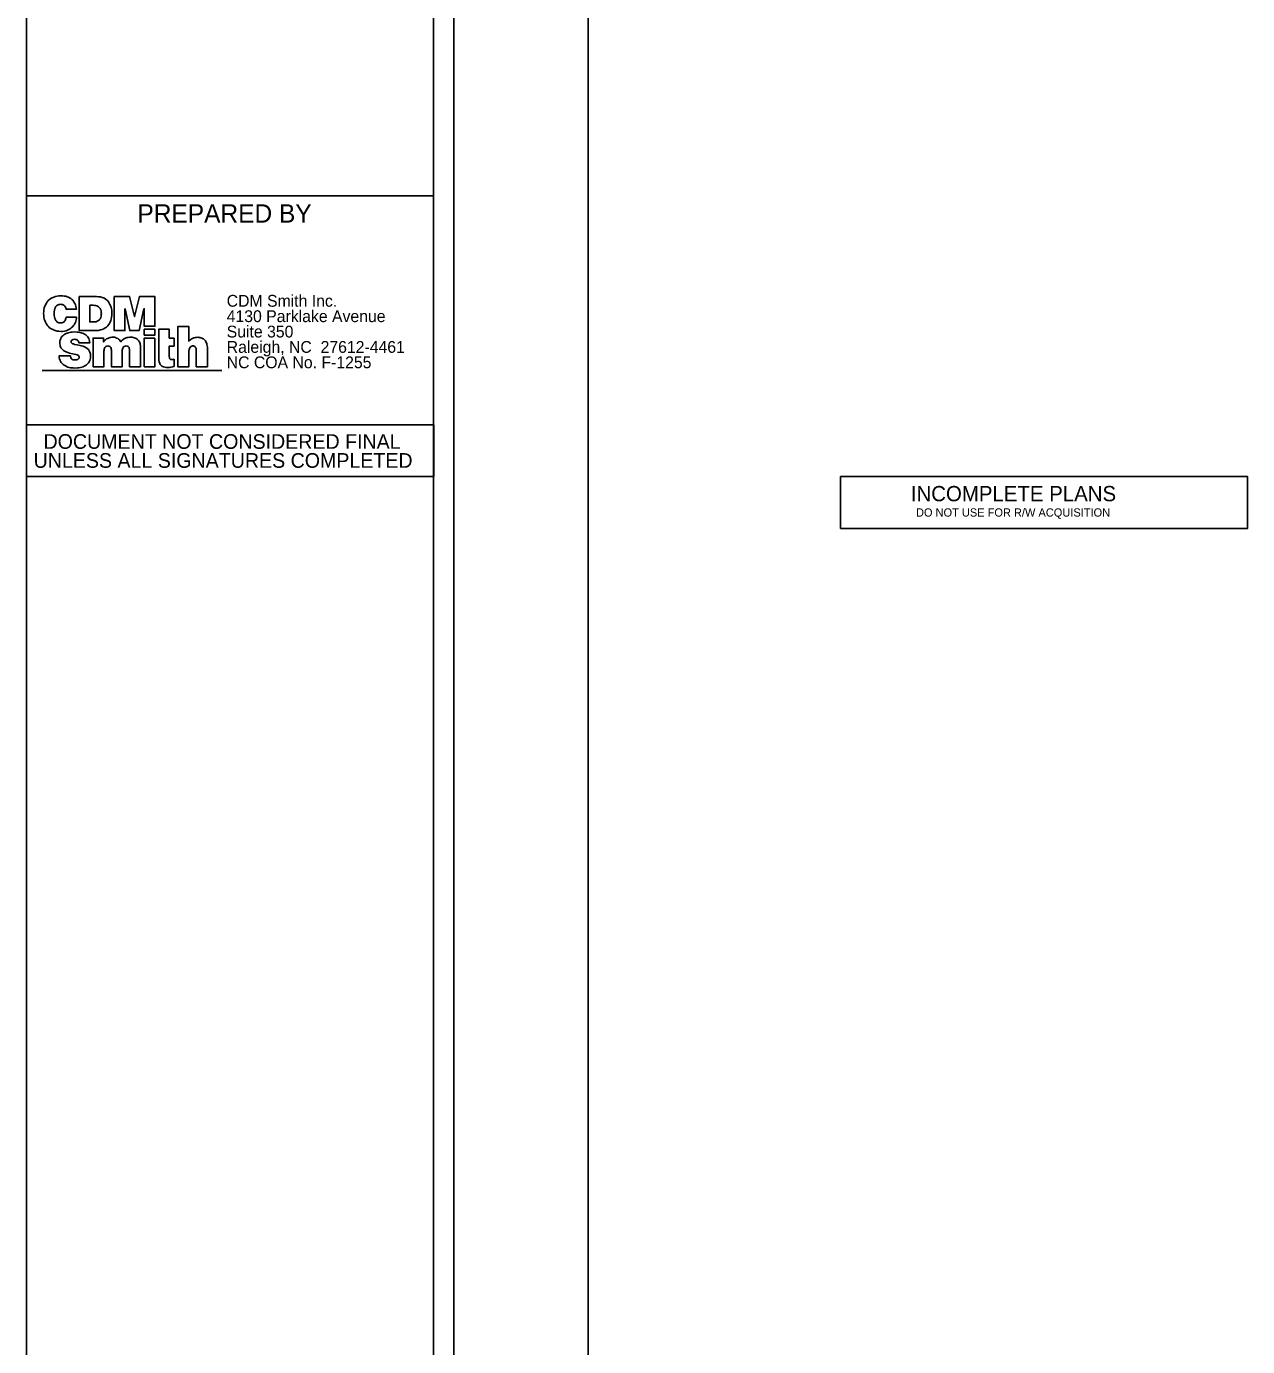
# Model space of a CAD drawing. Extents: x -2362 to 1945, y 0 to 1100.
# Drawn here: x 1562 to 1862, y 451.4 to 775.7 of the extents above; entities that cross this region are included whole.
import ezdxf

# ---------------------------------------------------------------- set-up
doc = ezdxf.new("R2010")
doc.units = 0
for name, color, linetype in [('Exist Utilities Telephone Test Hole SUE LOS A CELL', 7, 'Continuous'), ('Sheet PE Seal CELL', 7, 'Continuous'), ('Sheet_Data_Field_CELL', 7, 'Continuous'), ('z - Construction', 7, 'Continuous')]:
    doc.layers.add(name, color=color, linetype=linetype)

msp = doc.modelspace()

# ---------------------------------------------------------------- linework, layer by layer
at = {"layer": 'Exist Utilities Telephone Test Hole SUE LOS A CELL'}
msp.add_line((1699.98, 0), (1699.98, 1100), dxfattribs=at)
at = {"layer": 'Sheet PE Seal CELL'}
for p, q in [((1661.97, 734.06), (1561.97, 734.06)), ((1662.03, 677.87), (1562.03, 677.87))]:
    msp.add_line(p, q, dxfattribs=at)
for points in [[(1562.03, 677.87), (1662.03, 677.87), (1662.03, 665.13), (1562.03, 665.13)], [(1761.99, 665.13), (1861.99, 665.13), (1861.99, 652.39), (1761.99, 652.39)]]:
    msp.add_lwpolyline(points, close=True, dxfattribs=at)
at = {"layer": 'Sheet_Data_Field_CELL'}
msp.add_line((1565.85, 691.15), (1610.01, 691.15), dxfattribs=at)
for points in [[(1569.12, 703.6), (1569.04, 703.77), (1568.98, 703.94), (1568.87, 704.34), (1568.81, 704.73), (1568.78, 705.16), (1568.81, 705.59), (1568.87, 705.98), (1568.98, 706.38), (1569.04, 706.55), (1569.12, 706.72), (1569.23, 706.89), (1569.35, 707.04), (1569.46, 707.15), (1569.63, 707.26), (1569.77, 707.35), (1569.97, 707.41), (1570.17, 707.43), (1570.37, 707.46), (1570.57, 707.43), (1570.74, 707.41), (1570.88, 707.38), (1571.02, 707.32), (1571.17, 707.23), (1571.25, 707.15), (1571.42, 706.95), (1571.56, 706.75), (1571.65, 706.55), (1571.71, 706.35), (1571.73, 706.24), (1574.24, 706.24), (1574.18, 706.61), (1574.09, 706.98), (1574.01, 707.32), (1573.87, 707.63), (1573.72, 707.92), (1573.55, 708.2), (1573.35, 708.46), (1573.13, 708.66), (1572.87, 708.85), (1572.59, 709.05), (1572.3, 709.2), (1571.99, 709.31), (1571.62, 709.42), (1571.25, 709.48), (1570.85, 709.54), (1570.46, 709.54), (1569.97, 709.54), (1569.52, 709.45), (1569.09, 709.37), (1568.69, 709.22), (1568.33, 709.05), (1567.98, 708.85), (1567.64, 708.6), (1567.36, 708.34), (1567.1, 708.03), (1566.88, 707.72), (1566.68, 707.35), (1566.51, 706.95), (1566.36, 706.55), (1566.28, 706.1), (1566.22, 705.64), (1566.19, 705.16), (1566.22, 704.71), (1566.28, 704.25), (1566.36, 703.83), (1566.48, 703.43), (1566.65, 703.06), (1566.82, 702.69), (1567.05, 702.35), (1567.3, 702.03), (1567.59, 701.75), (1567.93, 701.52), (1568.27, 701.3), (1568.64, 701.13), (1569.04, 700.98), (1569.49, 700.87), (1569.94, 700.81), (1570.46, 700.78), (1570.88, 700.78), (1571.31, 700.87), (1571.71, 700.96), (1572.08, 701.1), (1572.42, 701.24), (1572.73, 701.44), (1573.01, 701.64), (1573.27, 701.89), (1573.5, 702.15), (1573.7, 702.4), (1573.87, 702.72), (1574.01, 703), (1574.12, 703.31), (1574.21, 703.63), (1574.26, 703.94), (1574.26, 704.25), (1571.73, 704.25), (1571.68, 703.97), (1571.59, 703.71), (1571.48, 703.48), (1571.34, 703.26), (1571.14, 703.09), (1570.94, 702.97), (1570.68, 702.89), (1570.37, 702.86), (1570.17, 702.89), (1569.97, 702.92), (1569.77, 702.97), (1569.63, 703.06), (1569.46, 703.17), (1569.35, 703.29), (1569.23, 703.43), (1569.12, 703.6)], [(1582.96, 704.71), (1582.96, 705.16), (1582.96, 705.56), (1582.93, 705.96), (1582.84, 706.35), (1582.76, 706.72), (1582.65, 707.06), (1582.5, 707.43), (1582.33, 707.75), (1582.13, 708.06), (1581.88, 708.34), (1581.62, 708.57), (1581.31, 708.8), (1580.97, 709), (1580.57, 709.14), (1580.15, 709.25), (1579.69, 709.31), (1579.18, 709.34), (1574.95, 709.34), (1574.95, 700.98), (1578.7, 700.98), (1579.21, 700.98), (1579.72, 701.04), (1580.17, 701.15), (1580.6, 701.27), (1580.97, 701.44), (1581.34, 701.64), (1581.65, 701.86), (1581.94, 702.12), (1582.16, 702.4), (1582.39, 702.72), (1582.56, 703.06), (1582.7, 703.43), (1582.82, 703.82), (1582.9, 704.25), (1582.96, 704.71)], [(1577.53, 707.21), (1578.36, 707.21), (1578.7, 707.18), (1578.98, 707.15), (1579.24, 707.06), (1579.46, 706.95), (1579.66, 706.84), (1579.83, 706.69), (1579.95, 706.55), (1580.06, 706.41), (1580.17, 706.24), (1580.23, 706.07), (1580.34, 705.73), (1580.37, 705.44), (1580.4, 705.22), (1580.37, 704.9), (1580.32, 704.56), (1580.23, 704.19), (1580.15, 704.02), (1580.06, 703.88), (1579.97, 703.71), (1579.83, 703.57), (1579.69, 703.46), (1579.52, 703.34), (1579.32, 703.26), (1579.09, 703.17), (1578.84, 703.14), (1578.55, 703.11), (1577.53, 703.11), (1577.53, 707.21)], [(1586.17, 706.35), (1586.23, 706.35), (1587.36, 700.98), (1589.64, 700.98), (1590.86, 706.35), (1590.91, 706.35), (1590.91, 702.03), (1593.56, 702.03), (1593.56, 709.34), (1589.75, 709.34), (1588.56, 704.42), (1588.53, 704.42), (1587.33, 709.34), (1583.56, 709.34), (1583.56, 700.98), (1586.17, 700.98), (1586.17, 706.35)], [(1577.73, 695.02), (1577.7, 695.24), (1577.64, 695.44), (1577.59, 695.67), (1577.5, 695.84), (1577.42, 696.01), (1577.3, 696.18), (1577.19, 696.32), (1576.91, 696.58), (1576.59, 696.81), (1576.28, 696.98), (1575.91, 697.12), (1575.54, 697.23), (1575.17, 697.32), (1574.43, 697.49), (1573.81, 697.6), (1573.55, 697.69), (1573.33, 697.77), (1573.21, 697.83), (1573.1, 697.91), (1573.01, 698.03), (1572.98, 698.2), (1573.01, 698.4), (1573.07, 698.54), (1573.16, 698.65), (1573.27, 698.74), (1573.41, 698.8), (1573.58, 698.82), (1573.89, 698.85), (1574.06, 698.82), (1574.24, 698.8), (1574.38, 698.71), (1574.52, 698.6), (1574.66, 698.48), (1574.77, 698.34), (1574.83, 698.17), (1574.86, 697.97), (1577.53, 697.97), (1577.5, 698.37), (1577.42, 698.71), (1577.3, 699.02), (1577.16, 699.31), (1576.96, 699.53), (1576.76, 699.76), (1576.54, 699.96), (1576.25, 700.1), (1576, 700.24), (1575.68, 700.36), (1575.4, 700.44), (1575.09, 700.53), (1574.75, 700.59), (1574.43, 700.61), (1573.81, 700.64), (1573.21, 700.61), (1572.9, 700.56), (1572.59, 700.53), (1572.27, 700.44), (1571.99, 700.36), (1571.71, 700.24), (1571.42, 700.1), (1571.17, 699.93), (1570.91, 699.73), (1570.71, 699.51), (1570.54, 699.28), (1570.4, 698.99), (1570.29, 698.68), (1570.2, 698.34), (1570.17, 697.94), (1570.2, 697.69), (1570.23, 697.43), (1570.29, 697.2), (1570.37, 696.98), (1570.46, 696.78), (1570.6, 696.58), (1570.74, 696.41), (1570.91, 696.24), (1571.11, 696.1), (1571.34, 695.95), (1571.59, 695.81), (1571.88, 695.7), (1572.19, 695.58), (1572.53, 695.47), (1573.33, 695.3), (1574.15, 695.13), (1574.43, 695.04), (1574.63, 694.96), (1574.77, 694.85), (1574.86, 694.73), (1574.92, 694.59), (1574.95, 694.42), (1574.92, 694.25), (1574.83, 694.11), (1574.72, 693.99), (1574.58, 693.91), (1574.43, 693.85), (1574.26, 693.79), (1573.95, 693.77), (1573.7, 693.79), (1573.47, 693.82), (1573.3, 693.91), (1573.16, 693.99), (1573.01, 694.16), (1572.9, 694.36), (1572.84, 694.53), (1572.81, 694.76), (1570, 694.76), (1570.03, 694.36), (1570.11, 693.99), (1570.23, 693.68), (1570.37, 693.37), (1570.54, 693.11), (1570.77, 692.86), (1571, 692.63), (1571.25, 692.46), (1571.54, 692.29), (1571.85, 692.15), (1572.16, 692.03), (1572.47, 691.95), (1572.81, 691.86), (1573.16, 691.83), (1573.5, 691.81), (1573.84, 691.78), (1574.55, 691.81), (1574.89, 691.86), (1575.23, 691.92), (1575.57, 692), (1575.88, 692.12), (1576.2, 692.23), (1576.48, 692.4), (1576.76, 692.57), (1576.99, 692.8), (1577.22, 693.03), (1577.39, 693.31), (1577.53, 693.62), (1577.64, 693.97), (1577.73, 694.33), (1577.73, 694.76), (1577.73, 695.02)], [(1593.56, 701.32), (1590.91, 701.32), (1590.91, 699.87), (1593.56, 699.87), (1593.56, 701.32)], [(1598.25, 699.16), (1597.08, 699.16), (1597.08, 701.32), (1594.47, 701.32), (1594.47, 699.16), (1594.47, 697.18), (1594.47, 694.7), (1594.47, 694.16), (1594.52, 693.68), (1594.61, 693.28), (1594.72, 692.94), (1594.86, 692.69), (1595.01, 692.49), (1595.2, 692.34), (1595.4, 692.2), (1595.66, 692.09), (1595.97, 692), (1596.34, 691.95), (1596.8, 691.95), (1597.11, 691.95), (1597.48, 692), (1597.88, 692.06), (1598.24, 692.17), (1598.24, 693.94), (1598.13, 693.91), (1597.93, 693.88), (1597.53, 693.85), (1597.39, 693.88), (1597.28, 693.96), (1597.22, 694.02), (1597.17, 694.08), (1597.14, 694.16), (1597.11, 694.31), (1597.08, 694.67), (1597.08, 697.18), (1598.25, 697.18), (1598.25, 699.16)], [(1606.29, 697.8), (1606.17, 698.06), (1606.09, 698.28), (1605.95, 698.48), (1605.8, 698.65), (1605.63, 698.82), (1605.46, 698.94), (1605.26, 699.05), (1605.04, 699.16), (1604.81, 699.22), (1604.58, 699.28), (1604.33, 699.31), (1604.07, 699.33), (1603.73, 699.31), (1603.42, 699.28), (1603.1, 699.22), (1602.76, 699.08), (1602.54, 698.94), (1602.34, 698.79), (1602.11, 698.6), (1601.88, 698.37), (1601.88, 701.95), (1599.15, 701.95), (1599.15, 692.09), (1601.88, 692.09), (1601.88, 695.5), (1601.88, 695.92), (1601.94, 696.32), (1602.05, 696.61), (1602.11, 696.72), (1602.17, 696.83), (1602.28, 696.98), (1602.45, 697.09), (1602.62, 697.18), (1602.79, 697.2), (1603.02, 697.2), (1603.19, 697.15), (1603.33, 697.06), (1603.47, 696.92), (1603.59, 696.78), (1603.64, 696.55), (1603.7, 696.29), (1603.7, 695.98), (1603.7, 692.09), (1606.43, 692.09), (1606.43, 696.58), (1606.43, 696.92), (1606.4, 697.23), (1606.34, 697.54), (1606.29, 697.8)], [(1581.08, 696.44), (1581.14, 696.64), (1581.25, 696.83), (1581.37, 696.98), (1581.51, 697.09), (1581.71, 697.18), (1581.96, 697.2), (1582.22, 697.18), (1582.45, 697.09), (1582.59, 696.98), (1582.7, 696.81), (1582.76, 696.61), (1582.82, 696.41), (1582.84, 696.18), (1582.84, 695.93), (1582.84, 692.12), (1585.52, 692.12), (1585.52, 695.93), (1585.54, 696.18), (1585.57, 696.44), (1585.63, 696.64), (1585.74, 696.83), (1585.86, 696.98), (1586, 697.09), (1586.2, 697.18), (1586.45, 697.2), (1586.71, 697.18), (1586.94, 697.09), (1587.08, 696.98), (1587.19, 696.81), (1587.25, 696.61), (1587.31, 696.41), (1587.33, 696.18), (1587.33, 695.93), (1587.33, 692.12), (1590, 692.12), (1590, 696.95), (1589.98, 697.37), (1589.95, 697.6), (1589.89, 697.8), (1589.83, 698), (1589.72, 698.2), (1589.61, 698.4), (1589.49, 698.57), (1589.32, 698.74), (1589.15, 698.88), (1588.95, 699.02), (1588.73, 699.14), (1588.5, 699.22), (1588.21, 699.28), (1587.93, 699.33), (1587.59, 699.33), (1587.28, 699.33), (1586.99, 699.31), (1586.74, 699.25), (1586.48, 699.19), (1586.28, 699.11), (1586.08, 699.02), (1585.77, 698.82), (1585.54, 698.62), (1585.37, 698.45), (1585.2, 698.23), (1585.03, 698.48), (1584.86, 698.71), (1584.63, 698.91), (1584.41, 699.05), (1584.12, 699.16), (1583.87, 699.28), (1583.58, 699.34), (1583.27, 699.34), (1582.93, 699.34), (1582.59, 699.28), (1582.28, 699.19), (1581.96, 699.08), (1581.68, 698.94), (1581.42, 698.74), (1581.2, 698.51), (1580.94, 698.19), (1580.94, 699.16), (1578.36, 699.16), (1578.35, 692.12), (1581.03, 692.12), (1581.03, 695.93), (1581.05, 696.18), (1581.08, 696.44)], [(1593.56, 699.16), (1590.91, 699.16), (1590.91, 692.09), (1593.56, 692.09), (1593.56, 699.16)]]:
    msp.add_lwpolyline(points, dxfattribs=at)
at = {"layer": 'z - Construction'}
for p, q in [((1561.97, 39.96), (1562, 1059.93)), ((1662, 39.96), (1662, 1059.91)), ((1667, 39.99), (1667, 1059.91))]:
    msp.add_line(p, q, dxfattribs=at)

# ---------------------------------------------------------------- texts
at = {"layer": 'Sheet PE Seal CELL'}
for s, height, p in [('PREPARED BY', 4.5, (1589.25, 727.51)), ('DOCUMENT NOT CONSIDERED FINAL', 3.6, (1566.18, 671.94)), ('UNLESS ALL SIGNATURES COMPLETED', 3.6, (1563.75, 667.28))]:
    msp.add_text(s, height=height, rotation=0, dxfattribs=at).set_placement(p)
for s, height, p in [('INCOMPLETE PLANS', 3.75, (1779.25, 659.06)), ('DO NOT USE FOR R/W ACQUISITION', 2.025, (1780.52, 655.29))]:
    msp.add_text(s, height=height, dxfattribs=at).set_placement(p)
at = {"layer": 'Sheet_Data_Field_CELL'}
for s, height, p in [('CDM Smith Inc.', 2.9003, (1611.18, 706.85)), ('4130 Parklake Avenue', 2.9003, (1611.18, 703.07)), ('Suite 350', 2.9, (1611.18, 699.29)), ('Raleigh, NC  27612-4461', 2.9003, (1611.18, 695.52)), ('NC COA No. F-1255', 2.9003, (1611.18, 691.74))]:
    msp.add_text(s, height=height, rotation=359.9982, dxfattribs=at).set_placement(p)

doc.saveas('drawing.dxf')
